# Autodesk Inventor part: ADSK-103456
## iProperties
Shininess: 0.0
Created: 2000-04
Part Number: ADSK-103456
Document SubType Name: Modeling
Stock Number: ADSK-103456
Density: 1 g/cm^3
Density: 0.0
Volumn: 0.0
Area: 0.0
PropertySet Name: Model Information
Control State: 0
Checked Out: False
Master: False
Author: gao
